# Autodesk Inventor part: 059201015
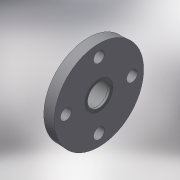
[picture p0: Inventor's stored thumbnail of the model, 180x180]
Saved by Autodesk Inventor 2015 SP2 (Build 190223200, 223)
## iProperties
Created: 2017-10
Part Number: 059201015
Material: Generic
Description: PLASSON THR. FIXED FLANGE PVC 1.1/2"
Document SubType Name: Modeling
Designer: KIM
Density: 1 g/cm^3
Appearance: Default
Author: KIM
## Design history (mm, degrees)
derived "059201.ipt"
feature "Solid1::059201.ipt"
tag "TaggingFeature1"
body "Solid1"
other parameters: "d0" = 32, "d3" = 148.5, "d14" = 18, "d15" = 55, "d16" = 32, "d17" = 0, "d19" = 360 deg, "d21" = 22, "d22" = 44.845, "d23" = 42.60275, "d25" = 0.44845, "d26" = 0.75, "d27" = 0.75, "d28" = 0.75, "d29" = 0.75, "d30" = 0.75, "d31" = 0.75, "d32" = 0.3, "d33" = 0, "d34" = 16, "d35" = 53.814, "H_" = 32, "S_" = 18, "lt_" = 22, "G_" = 44.845, "H_1" = 16
